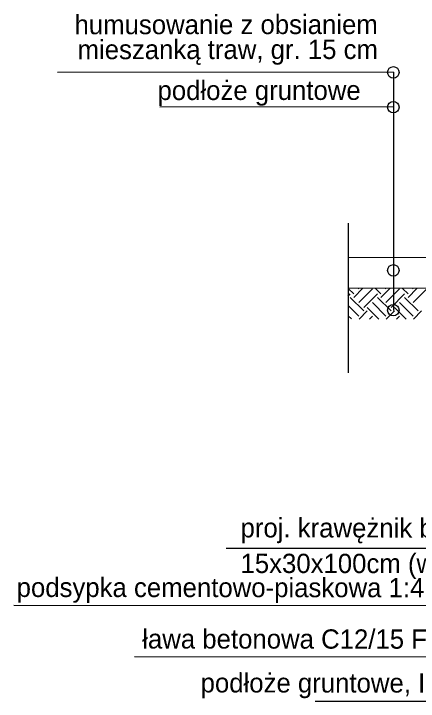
# Model space of a CAD drawing. Extents: x -219625893 to 7498339, y 5791790 to 5792761.
# Drawn here: x 7495162.15 to 7495188.44, y 5791845.42 to 5791890.05 of the extents above; entities that cross this region are included whole.
import ezdxf

# ---------------------------------------------------------------- set-up
doc = ezdxf.new("R2010")
doc.units = 0
for name, color, linetype in [('D_kons_wyp_grunt', 7, 'Continuous'), ('D_wymiary_500', 7, 'Continuous'), ('Level 10', 7, 'Continuous'), ('wymiary', 7, 'Continuous')]:
    doc.layers.add(name, color=color, linetype=linetype)

msp = doc.modelspace()

# ---------------------------------------------------------------- linework, layer by layer
at = {"layer": 'D_kons_wyp_grunt'}
for p, q in [((7495183.88, 5791876.451), (7495183.88, 5791866.749)), ((7495184.24, 5791871.862), (7495183.88, 5791872.221)), ((7495184.24, 5791871.641), (7495184.834, 5791872.235)), ((7495184.571, 5791872.193), (7495184.528, 5791872.237)), ((7495184.571, 5791871.309), (7495185.455, 5791872.193)), ((7495186.008, 5791871.862), (7495185.638, 5791872.231)), ((7495186.008, 5791871.641), (7495186.593, 5791872.226)), ((7495186.339, 5791872.193), (7495186.304, 5791872.228)), ((7495186.339, 5791871.309), (7495187.223, 5791872.193)), ((7495187.775, 5791871.862), (7495187.415, 5791872.222)), ((7495187.775, 5791871.641), (7495188.352, 5791872.218)), ((7495188.107, 5791872.193), (7495188.081, 5791872.219)), ((7495188.107, 5791871.309), (7495188.991, 5791872.193)), ((7495183.88, 5791871.723), (7495184.019, 5791871.862)), ((7495184.903, 5791870.757), (7495184.019, 5791871.641)), ((7495184.903, 5791870.978), (7495185.787, 5791871.862)), ((7495186.67, 5791870.757), (7495185.787, 5791871.641)), ((7495186.67, 5791870.978), (7495187.554, 5791871.862)), ((7495188.438, 5791870.757), (7495187.554, 5791871.641)), ((7495186.339, 5791870.425), (7495185.455, 5791871.309)), ((7495188.107, 5791870.425), (7495187.223, 5791871.309)), ((7495184.571, 5791870.425), (7495183.88, 5791871.116)), ((7495184.603, 5791870.236), (7495185.124, 5791870.757)), ((7495185.872, 5791870.23), (7495185.124, 5791870.978)), ((7495186.362, 5791870.227), (7495186.891, 5791870.757)), ((7495187.648, 5791870.221), (7495186.891, 5791870.978)), ((7495188.121, 5791870.219), (7495188.659, 5791870.757)), ((7495184.095, 5791870.239), (7495183.88, 5791870.453)), ((7495185.263, 5791870.233), (7495185.455, 5791870.425)), ((7495187.022, 5791870.224), (7495187.223, 5791870.425))]:
    msp.add_line(p, q, dxfattribs=at)
at = {"layer": 'D_wymiary_500'}
msp.add_line((7495195.442, 5791872.182), (7495183.88, 5791872.24), dxfattribs=at)
at = {"layer": 'Level 10'}
msp.add_line((7495195.452, 5791874.182), (7495183.88, 5791874.24), dxfattribs=at)
at = {"layer": 'wymiary'}
for p, q in [((7495186.818, 5791886.261), (7495164.983, 5791886.245)), ((7495186.818, 5791886.261), (7495186.818, 5791870.785)), ((7495186.818, 5791884.006), (7495171.645, 5791883.994)), ((7495175.955, 5791855.364), (7495196.983, 5791855.348)), ((7495162.147, 5791851.667), (7495196.983, 5791851.641)), ((7495169.992, 5791848.316), (7495196.983, 5791848.296)), ((7495181.727, 5791845.433), (7495196.983, 5791845.421))]:
    msp.add_line(p, q, dxfattribs=at)
for centre in [(7495186.818, 5791886.247), (7495186.818, 5791883.992), (7495186.818, 5791873.394), (7495186.818, 5791870.812)]:
    msp.add_circle(centre, 0.375, dxfattribs=at)

# ---------------------------------------------------------------- texts
for s, rotation, p in [('humusowanie z obsianiem ', 0.0429, (7495166.097, 5791888.724)), ('mieszanką traw, gr. 15 cm', 0.0429, (7495166.296, 5791887.105)), ('podłoże gruntowe ', 0.0429, (7495171.491, 5791884.452)), ('proj. krawężnik betonowy', 359.9571, (7495176.887, 5791856.059)), ('15x30x100cm (wystający)', 359.9571, (7495176.886, 5791853.748)), ('podsypka cementowo-piaskowa 1:4, gr.5cm', 359.9571, (7495162.336, 5791852.191)), ('ława betonowa C12/15 F=0,08m', 359.9571, (7495170.498, 5791848.846)), ('podłoże gruntowe, Is = 1,00', 359.9571, (7495174.292, 5791845.994))]:
    msp.add_text(s, height=1.25089, rotation=rotation, dxfattribs=at).set_placement(p)

doc.saveas('drawing.dxf')
